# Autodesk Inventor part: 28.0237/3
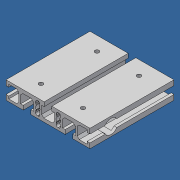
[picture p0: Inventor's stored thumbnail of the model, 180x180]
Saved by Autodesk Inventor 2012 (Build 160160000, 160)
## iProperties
Created: 2007-06
Part Number: 28.0237/3
Material: Aluminum-6061
Document SubType Name: Modeling
Designer: Andy Moles
Density: 2.71 g/cm^3
Description: L = 3.543" MILL TO 28.0237/3
Stock Number: 20.0995 PROFILE 90 X 19
Mass: 172.213 g
Surface Area: 440.776 cm^2
Volume: 63.5471 cm^3
Author: Andy Moles
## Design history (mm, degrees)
sketch "Sketch1"
  geometry: L1 (18.4, -9.5)-(18.4, -5) reference; L2 (17.9, -5)-(15.7, -5) reference; L3 (15.7, -5)-(15.7, 3.5) reference; L4 (15.7, 3.5)-(18, 5.8) reference; L5 (18, 5.8)-(27, 5.8) reference; L6 (27, 5.8)-(29.3, 3.5) reference; L7 (29.3, 3.5)-(29.3, -5) reference; L8 (26.6, -5)-(26.6, -9.5) reference; L9 (45, -9.5)-(26.9, -9.5) reference; L10 (45, -4.1)-(45, -9.5) reference; L11 (45, -4.1)-(42, -4.1) reference; L12 (42, -4.6)-(42, -6.8) reference; L13 (42, -6.8)-(33.5, -6.8) reference; L14 (33.5, -6.8)-(31.2, -4.5) reference; L15 (31.2, -4.5)-(31.2, 4.5) reference; L16 (31.2, 4.5)-(33.5, 6.8) reference; L17 (33.5, 6.8)-(42, 6.8) reference; L18 (42, 4.1)-(45, 4.1) reference; L19 (45, 9.5)-(45, 4.1) reference; L20 (4.4, 9.5)-(45, 9.5) reference; L21 (4.1, 9.5)-(4.1, 5) reference; L22 (4.6, 5)-(6.8, 5) reference; L23 (6.8, 5)-(6.8, -3.5) reference; L24 (6.8, -3.5)-(4.5, -5.8) reference; L25 (4.5, -5.8)-(-4.5, -5.8) reference; L26 (-4.5, -5.8)-(-6.8, -3.5) reference; L27 (-6.8, -3.5)-(-6.8, 5) reference; L28 (-4.1, 5)-(-4.1, 9.5) reference; L29 (-45, 4.1)-(-45, 9.5) reference; L30 (-45, 4.1)-(-42, 4.1) reference; L31 (-42, 4.1)-(-42, 6.8) reference; L32 (-42, 6.8)-(-33.5, 6.8) reference; L33 (-33.5, 6.8)-(-31.2, 4.5) reference; L34 (-31.2, 4.5)-(-31.2, -4.5) reference; L35 (-31.2, -4.5)-(-33.5, -6.8) reference; L36 (-33.5, -6.8)-(-42, -6.8) reference; L37 (-42, -6.8)-(-42, -4.1) reference; L38 (-42, -4.1)-(-45, -4.1) reference; L39 (-45, -9.5)-(-45, -4.1) reference; L40 (-26.6, -9.5)-(-26.6, -5) reference; L41 (-29.3, -5)-(-29.3, 3.5) reference; L42 (-29.3, 3.5)-(-27, 5.8) reference; L43 (-27, 5.8)-(-18, 5.8) reference; L44 (-18, 5.8)-(-15.7, 3.5) reference; L45 (-15.7, 3.5)-(-15.7, -5) reference; L46 (-15.7, -5)-(-17.9, -5) reference; L47 (-18.4, -5)-(-18.4, -9.5) reference; L48 (-18.1, -9.5)-(-18.4, -9.5) reference; L49 (-26.6, -9.5)-(-45, -9.5) reference; L50 (-17.9, -5)-(-18.4, -5) reference; L51 (-26.6, -5)-(-29.3, -5) reference; L52 (-6.8, 5)-(-4.1, 5) reference; L53 (4.1, 5)-(4.6, 5) reference; L54 (-45, 9.5)-(-4.1, 9.5) reference; L55 (4.1, 9.5)-(4.4, 9.5) reference; L56 (29.3, -5)-(26.6, -5) reference; L57 (18.4, -5)-(17.9, -5) reference; L58 (26.9, -9.5)-(26.6, -9.5) reference; L59 (18.4, -9.5)-(-18.1, -9.5) reference; L60 (42, 6.8)-(42, 4.1) reference; L61 (42, -4.1)-(42, -4.6) reference; L62 (-9.354, -2.59)-(-8.993, -2.95); L63 (-10.7, -7)-(-11.3, -7); L64 (-8.7, -3.657)-(-8.7, -5)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; A1 r 2.5 centre (-11, 0) between (-9.333, -1.863) and (-9.333, 1.863); A2 r 1 centre (-9.7, -3.657) between (-8.7, -3.657) and (-8.993, -2.95); A3 r 2 centre (-10.7, -5) between (-10.7, -7) and (-8.7, -5); A4 r 0.5 centre (-9, -2.236) between (-9.333, -1.863) and (-9.354, -2.59); A5 r 1 centre (-12.3, -3.657) between (-13.007, -2.95) and (-13.3, -3.657); A6 r 2.5 centre (-11, 0) between (-12.667, 1.863) and (-12.667, -1.863); A7 r 2 centre (-11.3, -5) between (-13.3, -5) and (-11.3, -7); A8 r 0.5 centre (-13, -2.236) between (-12.646, -2.59) and (-12.667, -1.863); A9 r 0.5 centre (-13, 2.236) between (-12.667, 1.863) and (-12.646, 2.59); A10 r 2 centre (-11.3, 5) between (-11.3, 7) and (-13.3, 5); A11 r 0.5 centre (-9, 2.236) between (-9.354, 2.59) and (-9.333, 1.863); A12 r 1 centre (-9.7, 3.657) between (-8.993, 2.95) and (-8.7, 3.657); A13 r 2 centre (-10.7, 5) between (-8.7, 5) and (-10.7, 7); A14 r 1 centre (-12.3, 3.657) between (-13.3, 3.657) and (-13.007, 2.95); A15 r 1 centre (12.3, 3.657) between (13.007, 2.95) and (13.3, 3.657); A16 r 0.5 centre (13, 2.236) between (12.646, 2.59) and (12.667, 1.863); A17 r 2 centre (11.3, 5) between (13.3, 5) and (11.3, 7); A18 r 0.5 centre (9, 2.236) between (9.333, 1.863) and (9.354, 2.59); A19 r 1 centre (9.7, 3.657) between (8.7, 3.657) and (8.993, 2.95); A20 r 2 centre (10.7, 5) between (10.7, 7) and (8.7, 5); A21 r 1 centre (9.7, -3.657) between (8.993, -2.95) and (8.7, -3.657); A22 r 2.5 centre (11, 0) between (9.333, 1.863) and (9.333, -1.863); A23 r 0.5 centre (9, -2.236) between (9.354, -2.59) and (9.333, -1.863); A24 r 2 centre (10.7, -5) between (8.7, -5) and (10.7, -7); A25 r 2.5 centre (11, 0) between (12.667, -1.863) and (12.667, 1.863); A26 r 0.5 centre (13, -2.236) between (12.667, -1.863) and (12.646, -2.59); A27 r 1 centre (12.3, -3.657) between (13.3, -3.657) and (13.007, -2.95); A28 r 2 centre (11.3, -5) between (11.3, -7) and (13.3, -5)
  constraints: 162 end point, 56 point on circle, 28 centre point, 28 horizontal, 23 vertical, 71 other
extrude "Extrusion1" new body sketch "Sketch1" stored distance "d0" = 90; taper "d1" = 0 deg
sketch "Sketch2"
  geometry: L1 (-26.6, -90)-(-26.6, 0) reference; L2 (63.4, -90)-(63.4, 0) reference; L3 (-8.2, 0)-(-26.6, 0) reference; L4 (-26.6, -90)-(-8.2, -90) reference; 5 further points
  constraints: 2 horizontal alignment, 2 vertical alignment
  dimensions: "d2" = 22.5 distance from line of point (-4.1, -15) L1; "d3" = 22.5 distance from line of point (40.9, -15) L2; "d4" = 15 distance from line of point (-4.1, -15) L3; "d5" = 15 distance from line of point (-4.1, -75) L4
hole "Hole1" sketch "Sketch2" at (40.9, -15), (40.9, -75), (-4.1, -75), (-4.1, -15) diameter "d6" = 4.5; stored, may be unused: countersink angle "d10" = 90 deg, drill point angle "d12" = 118 deg; dims "d7" = 6, "d8" = 4, "d9" = 2, "d11" = 4.5
sketch "Sketch3"
  geometry: L1 (0, 5.4)-(0, 0) reference; L2 (0, 0.4)-(0, -8.6) reference; 3 further points
  constraints: 1 horizontal alignment, 1 midpoint
  dimensions: "d13" = 22.5 distance from line of point (22.5, -4.1) L1
hole "Hole2" sketch "Sketch3" at (22.5, -4.1) diameter "d14" = 15; stored, may be unused: countersink angle "d18" = 90 deg, drill point angle "d20" = 0 deg; dims "d15" = 6, "d16" = 4, "d17" = 2, "d19" = 16
sketch "Sketch4"
  geometry: C1 r 7.5 at (-22.5, -4.1); A1 r 7.5 centre (-22.5, -4.1) between (-28.78, -8.2) and (-16.22, -8.2) reference; 1 further point
  constraints: 1 centre point, 1 coincident, 1 concentric
extrude "Extrusion2" cut sketch "Sketch4" distance "d21" = 16; taper "d22" = 0 deg
sketch "Sketch5"
  geometry: 3 further points
  constraints: 2 vertical alignment
  dimensions: "d23" = 22.5 distance of point (18.4, -67.5) point (18.4, -45); "d24" = 22.5 distance of point (18.4, -22.5) point (18.4, -45)
hole "Hole3" sketch "Sketch5" at (18.4, -22.5), (18.4, -67.5) diameter "d25" = 5.5; stored, may be unused: countersink angle "d29" = 90 deg, drill point angle "d31" = 118 deg; dims "d26" = 6, "d27" = 11.5, "d28" = 2, "d30" = 8
body "Solid1"
